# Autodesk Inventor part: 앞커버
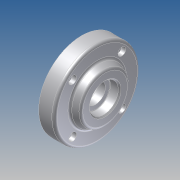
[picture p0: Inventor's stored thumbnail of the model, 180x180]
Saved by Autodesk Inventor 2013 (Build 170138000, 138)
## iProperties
Company: 한국ATC센터
Created: 2014-02
Part Number: 앞커버
Document SubType Name: Modeling
Designer: KYOUNG IL JANG
Density: 2.71 g/cm^3
Mass: 114.339 g
Surface Area: 117.889 cm^2
Volume: 42.1916 cm^3
Material: 알루미늄-6061
Vendor: CBT Solutions
Author: KYOUNG IL JANG
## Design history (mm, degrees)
sketch "스케치1"
  geometry: L1 (-11.5, 0)-(11.5, 0); L2 (11.5, 0)-(11.5, 22.5); L3 (11.5, 22.5)-(6.5, 22.5); L4 (6.5, 22.5)-(6.5, 32.5); L5 (6.5, 32.5)-(-5.5, 32.5); L6 (-5.5, 32.5)-(-5.5, 21); L7 (-5.5, 21)-(-11.5, 18.202); L8 (-11.5, 18.202)-(-11.5, 0); 2 further points
  constraints: 16 end point, 3 parallel, 3 perpendicular, 1 coincident, 1 horizontal, 1 midpoint
  dimensions: "d0" = 23 distance of L1.start L1.end; "d1" = 65 diameter of L5 L1; "d2" = 45 diameter of L3 L1; "d3" = 42 diameter of L6.end L1; "d4" = 115 deg angle of L7 L6; "d5" = 12 distance of L4.end L5.end; "d6" = 5 distance of L2.end L3.end
revolve "회전1" sketch "스케치1" stored, may be unused: angle "d7" = 90 deg
sketch "스케치2"
  geometry: L1 (0, 0)-(32.5, 0); L2 (0, 0)-(18.738, 18.738); 1 further point
  constraints: 4 end point, 1 horizontal, 1 horizontal alignment, 1 other
  dimensions: "d8" = 45 deg angle of L1 L2; "d9" = 26.5 distance of L1.start L2.end
hole "구멍1" sketch "스케치2" at (18.738, 18.738) diameter "d10" = 3.4; stored, may be unused: countersink angle "d14" = 90 deg, drill point angle "d16" = 118 deg; dims "d11" = 6, "d12" = 6, "d13" = 3.3, "d15" = 8
fillet "모깎기1" dims "d20" = 2
hole "구멍2" diameter "d23" = 15; stored, may be unused: countersink angle "d27" = 90 deg, drill point angle "d29" = 118 deg; dims "d21" = 10, "d22" = 10, "d24" = 6, "d25" = 32, "d26" = 10, "d28" = 8
hole "구멍3" diameter "d32" = 22; stored, may be unused: countersink angle "d36" = 90 deg, drill point angle "d38" = 0 deg; dims "d30" = 10, "d31" = 10, "d33" = 6, "d34" = 32, "d35" = 10, "d37" = 7.3
chamfer "모따기1" distance "d39" = 1; stored, may be unused: second distance "d40" = 2, angle "d41" = 45 deg
fillet "모깎기2" dims "d42" = 0.3
node "솔리드1"
pattern_circular "원형 패턴1" dims angle "d18" = 360 deg
